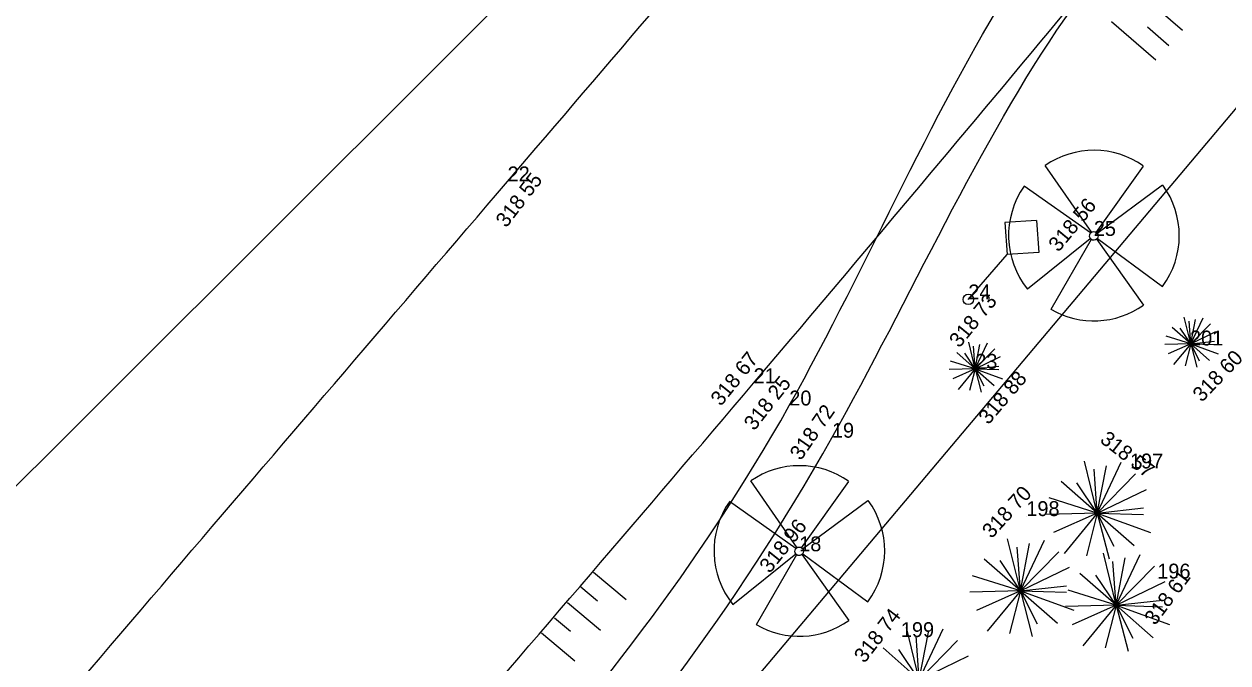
# Model space of a CAD drawing. Extents: x -742884 to -742543, y -1054677 to -1054433.
# Drawn here: x -742753.9 to -742729.63, y -1054501.01 to -1054488.13 of the extents above; entities that cross this region are included whole.
import ezdxf

# ---------------------------------------------------------------- set-up
doc = ezdxf.new("R2010")
doc.units = 0
for name, color, linetype in [('Vrstva 1', 7, 'Continuous'), ('Vrstva 10', 7, 'Continuous'), ('Vrstva 11', 7, 'Continuous'), ('Vrstva 14', 7, 'Continuous'), ('Vrstva 2', 7, 'Continuous'), ('Vrstva 3', 7, 'Continuous'), ('Vrstva 4', 7, 'Continuous'), ('Vrstva 50', 7, 'Continuous')]:
    doc.layers.add(name, color=color, linetype=linetype)

# ---------------------------------------------------------------- blocks, each defined once
blk = doc.blocks.new('Z15')
at = {"layer": 'Vrstva 2'}
for p, q in [((-10, 2), (-8, 6)), ((-10, -2), (-10, 2)), ((-8, 6), (-6, 8)), ((-6, 8), (-2, 10)), ((-2, 10), (2, 10)), ((2, 10), (6, 8)), ((6, 8), (8, 6)), ((8, 6), (10, 2)), ((10, 2), (10, -2)), ((-8, -6), (-10, -2)), ((-6, -8), (-8, -6)), ((-2, -10), (-6, -8)), ((2, -10), (-2, -10)), ((6, -8), (2, -10)), ((8, -6), (6, -8)), ((10, -2), (8, -6))]:
    blk.add_line(p, q, dxfattribs=at)

msp = doc.modelspace()

# ---------------------------------------------------------------- linework, layer by layer
at = {"layer": 'Vrstva 1'}
for p, q in [((-742744.15, -1054491.3), (-742744.15, -1054491.3)), ((-742732.33, -1054492.4), (-742732.33, -1054492.4)), ((-742734.86, -1054493.68), (-742734.86, -1054493.68)), ((-742730.39, -1054494.61), (-742730.39, -1054494.61)), ((-742734.72, -1054495.08), (-742734.72, -1054495.08)), ((-742739.19, -1054495.37), (-742739.19, -1054495.37)), ((-742738.47, -1054495.82), (-742738.47, -1054495.82)), ((-742737.61, -1054496.47), (-742737.61, -1054496.47)), ((-742731.6, -1054497.09), (-742731.6, -1054497.09)), ((-742733.69, -1054498.05), (-742733.69, -1054498.05)), ((-742738.27, -1054498.76), (-742738.27, -1054498.76)), ((-742731.05, -1054499.31), (-742731.05, -1054499.31)), ((-742736.22, -1054500.49), (-742736.22, -1054500.49))]:
    msp.add_line(p, q, dxfattribs=at)
at = {"layer": 'Vrstva 10'}
for p, q in [((-742732.37, -1054492.331), (-742733.308, -1054490.98)), ((-742732.281, -1054492.331), (-742731.33, -1054490.993)), ((-742732.395, -1054492.341), (-742733.734, -1054491.399)), ((-742732.266, -1054492.351), (-742730.944, -1054491.373)), ((-742732.4, -1054492.459), (-742733.668, -1054493.477)), ((-742732.382, -1054492.475), (-742733.197, -1054493.883)), ((-742732.272, -1054492.47), (-742731.328, -1054493.798)), ((-742732.258, -1054492.45), (-742730.944, -1054493.419)), ((-742730.375, -1054494.576), (-742730.508, -1054494.037)), ((-742730.375, -1054494.576), (-742730.127, -1054494.051)), ((-742730.375, -1054494.576), (-742730.282, -1054494.085)), ((-742730.375, -1054494.576), (-742730.75, -1054494.247)), ((-742730.375, -1054494.576), (-742730.586, -1054494.264)), ((-742730.375, -1054494.576), (-742730.409, -1054494.122)), ((-742730.375, -1054494.576), (-742729.979, -1054494.171)), ((-742730.375, -1054494.576), (-742729.867, -1054494.331)), ((-742734.72, -1054495.08), (-742734.853, -1054494.541)), ((-742734.72, -1054495.08), (-742734.472, -1054494.555)), ((-742730.375, -1054494.576), (-742730.901, -1054494.59)), ((-742730.375, -1054494.576), (-742730.874, -1054494.419)), ((-742730.375, -1054494.576), (-742730.83, -1054494.778)), ((-742730.375, -1054494.576), (-742730.72, -1054494.994)), ((-742730.375, -1054494.576), (-742730.49, -1054495.017)), ((-742730.379, -1054494.574), (-742730.379, -1054494.574)), ((-742730.375, -1054494.576), (-742729.898, -1054494.523)), ((-742730.375, -1054494.576), (-742730.375, -1054494.576)), ((-742730.375, -1054494.576), (-742730.204, -1054494.917)), ((-742730.375, -1054494.576), (-742729.825, -1054494.776)), ((-742730.375, -1054494.576), (-742729.898, -1054494.592)), ((-742730.375, -1054494.576), (-742729.994, -1054494.911)), ((-742730.375, -1054494.576), (-742730.253, -1054495.05)), ((-742730.375, -1054494.576), (-742730.375, -1054494.576)), ((-742734.72, -1054495.08), (-742735.095, -1054494.751)), ((-742734.72, -1054495.08), (-742734.931, -1054494.768)), ((-742734.72, -1054495.08), (-742734.754, -1054494.626)), ((-742734.72, -1054495.08), (-742734.627, -1054494.589)), ((-742734.72, -1054495.08), (-742734.324, -1054494.675)), ((-742734.72, -1054495.08), (-742735.219, -1054494.923)), ((-742734.72, -1054495.08), (-742734.212, -1054494.835)), ((-742734.72, -1054495.08), (-742734.243, -1054495.027)), ((-742734.72, -1054495.08), (-742735.246, -1054495.094)), ((-742734.72, -1054495.08), (-742735.175, -1054495.282)), ((-742734.72, -1054495.08), (-742735.065, -1054495.498)), ((-742734.72, -1054495.08), (-742734.835, -1054495.521)), ((-742734.724, -1054495.078), (-742734.724, -1054495.078)), ((-742734.72, -1054495.08), (-742734.72, -1054495.08)), ((-742734.72, -1054495.08), (-742734.549, -1054495.421)), ((-742734.72, -1054495.08), (-742734.17, -1054495.28)), ((-742734.72, -1054495.08), (-742734.243, -1054495.096)), ((-742734.72, -1054495.08), (-742734.339, -1054495.415)), ((-742734.72, -1054495.08), (-742734.598, -1054495.554)), ((-742734.72, -1054495.08), (-742734.72, -1054495.08)), ((-742732.26, -1054497.99), (-742732.517, -1054496.94)), ((-742732.26, -1054497.99), (-742731.775, -1054496.965)), ((-742732.26, -1054497.99), (-742732.324, -1054497.106)), ((-742732.26, -1054497.99), (-742732.076, -1054497.034)), ((-742732.26, -1054497.99), (-742731.487, -1054497.199)), ((-742738.31, -1054498.691), (-742739.248, -1054497.34)), ((-742738.221, -1054498.691), (-742737.27, -1054497.353)), ((-742732.26, -1054497.99), (-742732.989, -1054497.35)), ((-742732.26, -1054497.99), (-742732.67, -1054497.379)), ((-742732.26, -1054497.99), (-742733.229, -1054497.683)), ((-742732.26, -1054497.99), (-742731.268, -1054497.511)), ((-742738.335, -1054498.701), (-742739.674, -1054497.759)), ((-742738.206, -1054498.711), (-742736.884, -1054497.733)), ((-742732.26, -1054497.99), (-742731.328, -1054497.884)), ((-742732.26, -1054497.99), (-742733.282, -1054498.016)), ((-742732.26, -1054497.99), (-742733.145, -1054498.383)), ((-742732.26, -1054497.99), (-742732.93, -1054498.804)), ((-742732.26, -1054497.99), (-742732.48, -1054498.849)), ((-742732.264, -1054497.984), (-742732.264, -1054497.984)), ((-742732.26, -1054497.99), (-742732.26, -1054497.99)), ((-742732.26, -1054497.99), (-742731.924, -1054498.654)), ((-742732.26, -1054497.99), (-742731.185, -1054498.379)), ((-742732.26, -1054497.99), (-742731.328, -1054498.018)), ((-742732.26, -1054497.99), (-742731.514, -1054498.643)), ((-742732.26, -1054497.99), (-742732.02, -1054498.912)), ((-742732.26, -1054497.99), (-742732.26, -1054497.99)), ((-742733.81, -1054499.56), (-742734.067, -1054498.51)), ((-742733.81, -1054499.56), (-742733.874, -1054498.676)), ((-742733.81, -1054499.56), (-742733.325, -1054498.535)), ((-742733.81, -1054499.56), (-742733.626, -1054498.604)), ((-742738.34, -1054498.819), (-742739.608, -1054499.837)), ((-742738.322, -1054498.835), (-742739.137, -1054500.243)), ((-742738.212, -1054498.83), (-742737.268, -1054500.158)), ((-742738.198, -1054498.81), (-742736.884, -1054499.779)), ((-742733.81, -1054499.56), (-742734.539, -1054498.92)), ((-742733.81, -1054499.56), (-742733.037, -1054498.769)), ((-742731.88, -1054499.85), (-742732.137, -1054498.8)), ((-742731.88, -1054499.85), (-742731.395, -1054498.825)), ((-742731.88, -1054499.85), (-742731.696, -1054498.894)), ((-742733.81, -1054499.56), (-742734.22, -1054498.949)), ((-742733.81, -1054499.56), (-742732.818, -1054499.081)), ((-742731.88, -1054499.85), (-742731.944, -1054498.966)), ((-742731.88, -1054499.85), (-742731.107, -1054499.059)), ((-742733.81, -1054499.56), (-742734.779, -1054499.253)), ((-742731.88, -1054499.85), (-742732.609, -1054499.21)), ((-742731.88, -1054499.85), (-742732.29, -1054499.239)), ((-742731.88, -1054499.85), (-742730.888, -1054499.371)), ((-742733.81, -1054499.56), (-742734.832, -1054499.586)), ((-742733.81, -1054499.56), (-742734.695, -1054499.953)), ((-742733.81, -1054499.56), (-742734.48, -1054500.374)), ((-742733.81, -1054499.56), (-742734.03, -1054500.419)), ((-742733.814, -1054499.554), (-742733.814, -1054499.554)), ((-742733.81, -1054499.56), (-742732.878, -1054499.454)), ((-742733.81, -1054499.56), (-742733.81, -1054499.56)), ((-742733.81, -1054499.56), (-742733.474, -1054500.224)), ((-742733.81, -1054499.56), (-742732.735, -1054499.949)), ((-742733.81, -1054499.56), (-742732.878, -1054499.588)), ((-742733.81, -1054499.56), (-742733.064, -1054500.213)), ((-742733.81, -1054499.56), (-742733.57, -1054500.482)), ((-742733.81, -1054499.56), (-742733.81, -1054499.56)), ((-742731.88, -1054499.85), (-742732.849, -1054499.543)), ((-742731.88, -1054499.85), (-742732.902, -1054499.876)), ((-742731.88, -1054499.85), (-742732.765, -1054500.243)), ((-742731.88, -1054499.85), (-742732.55, -1054500.664)), ((-742731.88, -1054499.85), (-742732.1, -1054500.709)), ((-742731.884, -1054499.844), (-742731.884, -1054499.844)), ((-742731.88, -1054499.85), (-742730.948, -1054499.744)), ((-742731.88, -1054499.85), (-742731.88, -1054499.85)), ((-742731.88, -1054499.85), (-742731.544, -1054500.514)), ((-742731.88, -1054499.85), (-742730.805, -1054500.239)), ((-742731.88, -1054499.85), (-742730.948, -1054499.878)), ((-742731.88, -1054499.85), (-742731.134, -1054500.503)), ((-742731.88, -1054499.85), (-742731.64, -1054500.772)), ((-742731.88, -1054499.85), (-742731.88, -1054499.85)), ((-742735.85, -1054501.35), (-742736.107, -1054500.3)), ((-742735.85, -1054501.35), (-742735.365, -1054500.325)), ((-742735.85, -1054501.35), (-742735.666, -1054500.394)), ((-742735.85, -1054501.35), (-742735.914, -1054500.466)), ((-742735.85, -1054501.35), (-742735.077, -1054500.559)), ((-742735.85, -1054501.35), (-742736.579, -1054500.71)), ((-742735.85, -1054501.35), (-742736.26, -1054500.739)), ((-742735.85, -1054501.35), (-742734.858, -1054500.871))]:
    msp.add_line(p, q, dxfattribs=at)
for centre, radius, start, end in [((-742732.326, -1054492.394), 1.72, 54.7465, 124.8105), ((-742732.328, -1054492.39), 1.721, 144.8767, 218.9336), ((-742732.326, -1054492.394), 1.72, 323.4756, 36.2971), ((-742732.326, -1054492.394), 1.72, 239.6151, 305.4552), ((-742738.266, -1054498.754), 1.72, 54.7465, 124.8105), ((-742738.268, -1054498.75), 1.721, 144.8767, 218.9336), ((-742738.266, -1054498.754), 1.72, 323.4756, 36.2971), ((-742738.266, -1054498.754), 1.72, 239.6151, 305.4552)]:
    msp.add_arc(centre, radius, start, end, dxfattribs=at)
at = {"layer": 'Vrstva 11'}
for p, q in [((-742730.544, -1054488.26), (-742731.459, -1054487.465)), ((-742731.972, -1054488.075), (-742731.082, -1054488.852)), ((-742731.249, -1054488.183), (-742730.816, -1054488.559)), ((-742741.762, -1054499.737), (-742742.419, -1054499.187)), ((-742742.339, -1054499.768), (-742742.676, -1054499.487)), ((-742742.939, -1054499.794), (-742742.275, -1054500.348)), ((-742743.202, -1054500.1), (-742742.879, -1054500.371)), ((-742743.465, -1054500.406), (-742742.796, -1054500.967))]:
    msp.add_line(p, q, dxfattribs=at)
for points in [[(-742777.63, -1054542.12), (-742764.61, -1054526.83), (-742751.7, -1054511.56), (-742738.47, -1054495.82), (-742727.02, -1054482.18), (-742726.38, -1054482.19), (-742725.15, -1054482.94)], [(-742776.7, -1054542.68), (-742764.01, -1054527.79), (-742751.11, -1054512.75), (-742737.61, -1054496.47), (-742726.42, -1054483.98), (-742725.9, -1054484.03), (-742714, -1054491.86), (-742704.819, -1054497.481), (-742700.94, -1054500.269), (-742696.44, -1054503.39), (-742688.83, -1054509.5), (-742682.54, -1054514.17), (-742675.15, -1054519.77), (-742673.01, -1054522.11), (-742671.05, -1054524.7)]]:
    msp.add_spline(points, degree=3, dxfattribs=at)
at = {"layer": 'Vrstva 14'}
for p, q in [((-742733.483, -1054492.089), (-742734.124, -1054492.132)), ((-742734.124, -1054492.132), (-742734.078, -1054492.774)), ((-742733.483, -1054492.089), (-742733.441, -1054492.734)), ((-742733.441, -1054492.734), (-742734.078, -1054492.774))]:
    msp.add_line(p, q, dxfattribs=at)
msp.add_lwpolyline([(-742734.86, -1054493.68), (-742734.078, -1054492.774)], dxfattribs=at)
msp.add_circle((-742734.86, -1054493.68), 0.105, dxfattribs=at)
at = {"layer": 'Vrstva 4'}
for points in [[(-742783.23, -1054536.93), (-742770.7, -1054522.44), (-742757.28, -1054506.67), (-742744.15, -1054491.3), (-742731.95, -1054477.03), (-742724.73, -1054468.59)], [(-742778.49, -1054541.37), (-742765.63, -1054526.43), (-742752.39, -1054510.77), (-742739.19, -1054495.37), (-742727.3, -1054481.14)]]:
    msp.add_spline(points, degree=3, dxfattribs=at)
at = {"layer": 'Vrstva 50'}
for points in [[(-742771.57, -1054517.32), (-742758.54, -1054501.91), (-742742.39, -1054485.79), (-742708.76, -1054445.064)], [(-742724.95, -1054484.46), (-742747.39, -1054511.11), (-742766.3, -1054533.47), (-742786.45, -1054556.28), (-742796.57, -1054568.72)]]:
    msp.add_lwpolyline(points, dxfattribs=at)

# ---------------------------------------------------------------- block references
at = {"layer": 'Vrstva 10', "xscale": 0.008601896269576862, "yscale": 0.008601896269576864, "rotation": -30.671756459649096}
for p in [(-742732.33, -1054492.4), (-742738.27, -1054498.76)]:
    msp.add_blockref('Z15', p, dxfattribs=at)

# ---------------------------------------------------------------- texts
at = {"layer": 'Vrstva 2'}
for s, p in [('22', (-742744.15, -1054491.3)), ('25', (-742732.33, -1054492.4)), ('24', (-742734.86, -1054493.68)), ('201', (-742730.39, -1054494.61)), ('23', (-742734.72, -1054495.08)), ('21', (-742739.19, -1054495.37)), ('20', (-742738.47, -1054495.82)), ('19', (-742737.61, -1054496.47)), ('197', (-742731.6, -1054497.09)), ('198', (-742733.69, -1054498.05)), ('18', (-742738.27, -1054498.76)), ('196', (-742731.05, -1054499.31)), ('199', (-742736.22, -1054500.49))]:
    msp.add_text(s, height=0.3, dxfattribs=at).set_placement(p)
at = {"layer": 'Vrstva 3'}
for s, rotation, p in [('318 55 ', 52.6242, (-742744.177, -1054492.25)), ('318 56 ', 50.4657, (-742733.041, -1054492.741)), ('318 73 ', 50.7296, (-742735.041, -1054494.673)), ('318 67 ', 51.1809, (-742739.849, -1054495.849)), ('318 60 ', 46.2075, (-742730.15, -1054495.767)), ('318 25 ', 52.0035, (-742739.175, -1054496.343)), ('318 88 ', 49.6729, (-742734.455, -1054496.222)), ('318 72 ', 55.1591, (-742738.237, -1054496.944)), ('318 57 ', 322.0392, (-742732.225, -1054496.546)), ('318 70 ', 47.5261, (-742734.391, -1054498.518)), ('318 96 ', 51.4416, (-742738.864, -1054499.22)), ('318 61 ', 53.4034, (-742731.094, -1054500.269)), ('318 74 ', 52.2492, (-742736.954, -1054501.032))]:
    msp.add_text(s, height=0.3, rotation=rotation, dxfattribs=at).set_placement(p)

doc.saveas('drawing.dxf')
